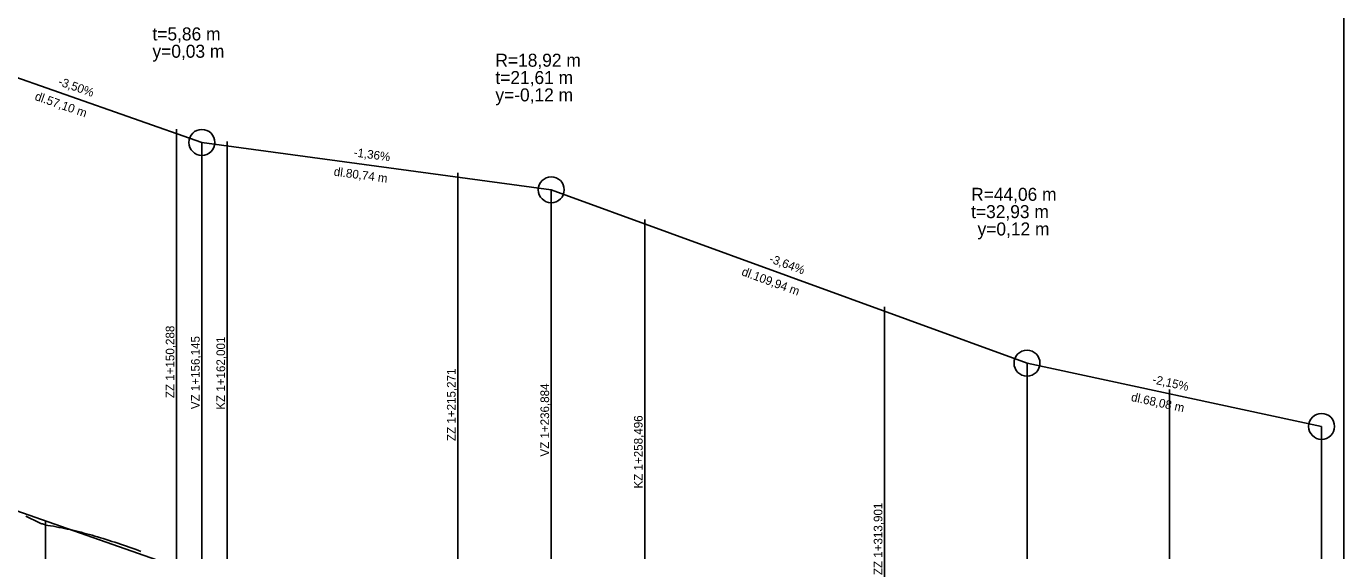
# Model space of a CAD drawing. Extents: x -632716 to -629545, y -1094726 to -1088285.
# Drawn here: x -631495.2 to -631190.8, y -1093447.3 to -1093326.3 of the extents above; entities that cross this region are included whole.
import ezdxf

# ---------------------------------------------------------------- set-up
doc = ezdxf.new("R2010")
doc.units = 0
for name, color, linetype in [('20', 7, 'Continuous'), ('Default', 7, 'Continuous'), ('SKLONY_NIVELETA', 7, 'Continuous'), ('SKLONY_POPIS', 7, 'Continuous'), ('TECNY_NIVELETA', 7, 'Continuous'), ('VOZOVKA', 7, 'Continuous')]:
    doc.layers.add(name, color=color, linetype=linetype)

msp = doc.modelspace()

# ---------------------------------------------------------------- linework, layer by layer
at = {"layer": '20'}
for points in [[(-631190.75, -1093221.74), (-631190.75, -1093521.74), (-631190.75, -1093571.74), (-631190.75, -1093511.74)], [(-631490.75, -1093440.44), (-631490.75, -1093521.74), (-631490.75, -1093571.74), (-631490.75, -1093511.74)]]:
    msp.add_lwpolyline(points, dxfattribs=at)
at = {"layer": 'Default'}
msp.add_line((-631506.42, -1093434.96), (-631460.47, -1093451.04), dxfattribs=at)
msp.add_line((-631506.42, -1093434.96), (-631460.47, -1093451.04), dxfattribs=at)
at = {"layer": 'SKLONY_NIVELETA'}
for p, q in [((-631511.71, -1093333.11), (-631454.61, -1093353.09)), ((-631454.61, -1093353.09), (-631454.61, -1093571.74)), ((-631454.61, -1093353.09), (-631373.87, -1093364.03)), ((-631373.87, -1093364.03), (-631373.87, -1093571.74)), ((-631373.87, -1093364.03), (-631263.93, -1093404.05)), ((-631263.93, -1093404.05), (-631263.93, -1093571.74)), ((-631263.93, -1093404.05), (-631195.85, -1093418.65)), ((-631195.85, -1093418.65), (-631195.85, -1093571.74)), ((-631506.42, -1093434.96), (-631460.47, -1093451.04))]:
    msp.add_line(p, q, dxfattribs=at)
for centre in [(-631454.61, -1093353.09), (-631373.87, -1093364.03), (-631263.93, -1093404.05), (-631195.85, -1093418.65)]:
    msp.add_circle(centre, 3, dxfattribs=at)
at = {"layer": 'TECNY_NIVELETA'}
for p, q in [((-631460.47, -1093451.04), (-631460.47, -1093350.04)), ((-631454.61, -1093353.09), (-631454.61, -1093353.09)), ((-631448.75, -1093453.89), (-631448.75, -1093352.89)), ((-631395.48, -1093461.11), (-631395.48, -1093360.11)), ((-631373.87, -1093364.03), (-631373.87, -1093364.03)), ((-631352.26, -1093471.9), (-631352.26, -1093370.9)), ((-631296.85, -1093492.07), (-631296.85, -1093391.07)), ((-631263.93, -1093404.05), (-631263.93, -1093404.05)), ((-631231, -1093511.11), (-631231, -1093410.11)), ((-631195.85, -1093418.65), (-631195.85, -1093418.65))]:
    msp.add_line(p, q, dxfattribs=at)
at = {"layer": 'VOZOVKA'}
msp.add_lwpolyline([(-631495.3, -1093439.35), (-631494.67, -1093439.66), (-631494.03, -1093439.98), (-631493.39, -1093440.3), (-631492.75, -1093440.62), (-631492.11, -1093440.95), (-631491.82, -1093441.09), (-631491.62, -1093441.13), (-631491.47, -1093441.17), (-631491.23, -1093441.24), (-631490.83, -1093441.37), (-631490.68, -1093441.43), (-631490.19, -1093441.51), (-631489.56, -1093441.61), (-631488.92, -1093441.72), (-631488.28, -1093441.84), (-631487.64, -1093441.96), (-631487, -1093442.09), (-631486.36, -1093442.22), (-631485.72, -1093442.35), (-631485.08, -1093442.49), (-631484.44, -1093442.64), (-631483.81, -1093442.79), (-631483.17, -1093442.94), (-631482.53, -1093443.1), (-631481.89, -1093443.27), (-631481.25, -1093443.44), (-631480.61, -1093443.61), (-631479.97, -1093443.79), (-631479.33, -1093443.97), (-631478.7, -1093444.16), (-631478.06, -1093444.35), (-631477.39, -1093444.55), (-631476.72, -1093444.76), (-631476.06, -1093444.97), (-631475.39, -1093445.19), (-631474.72, -1093445.41), (-631474.06, -1093445.64), (-631473.39, -1093445.86), (-631472.72, -1093446.09), (-631472.06, -1093446.32), (-631471.39, -1093446.56), (-631470.72, -1093446.79), (-631470.06, -1093447.03), (-631469.39, -1093447.26), (-631468.72, -1093447.5)], dxfattribs=at)

# ---------------------------------------------------------------- texts
at = {"layer": 'SKLONY_POPIS'}
for s, p in [('t=5,86 m', (-631466.03, -1093329.54)), ('y=0,03 m', (-631466.03, -1093333.54)), ('R=18,92 m', (-631386.78, -1093335.61)), ('t=21,61 m', (-631386.78, -1093339.61)), ('y=-0,12 m', (-631386.78, -1093343.61)), ('R=44,06 m', (-631276.84, -1093366.57)), ('t=32,93 m', (-631276.84, -1093370.57)), ('y=0,12 m', (-631275.35, -1093374.57))]:
    msp.add_text(s, height=3, dxfattribs=at).set_placement(p)
for s, rotation, p in [('-3,50%', 340.71, (-631487.98, -1093339.82)), ('dl.57,10 m', 340.71, (-631493.38, -1093343.23)), ('-1,36%', 352.2819, (-631419.62, -1093356.32)), ('dl.80,74 m', 352.2819, (-631424.22, -1093360.74)), ('-3,64%', 340.0002, (-631323.68, -1093380.71)), ('dl.109,94 m', 340.0002, (-631330.05, -1093383.71)), ('ZZ 1+150,288', 90, (-631460.97, -1093412.12)), ('VZ 1+156,145', 90, (-631455.11, -1093414.67)), ('KZ 1+162,001', 90, (-631449.25, -1093414.8)), ('ZZ 1+215,271', 90, (-631395.98, -1093422.02)), ('-2,15%', 347.8932, (-631235.08, -1093408.7)), ('VZ 1+236,884', 90, (-631374.37, -1093425.62)), ('dl.68,08 m', 347.8932, (-631240.01, -1093412.76)), ('KZ 1+258,496', 90, (-631352.76, -1093432.98)), ('ZZ 1+313,901', 90, (-631297.35, -1093452.98))]:
    msp.add_text(s, height=2, rotation=rotation, dxfattribs=at).set_placement(p)

doc.saveas('drawing.dxf')
